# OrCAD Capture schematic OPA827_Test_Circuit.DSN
size A; title: OPA827 Low-Noise, High-Precision, JFET-Input Operational; rev: 1.3; note: Datasheet: SBOS376I  EVM: N/A
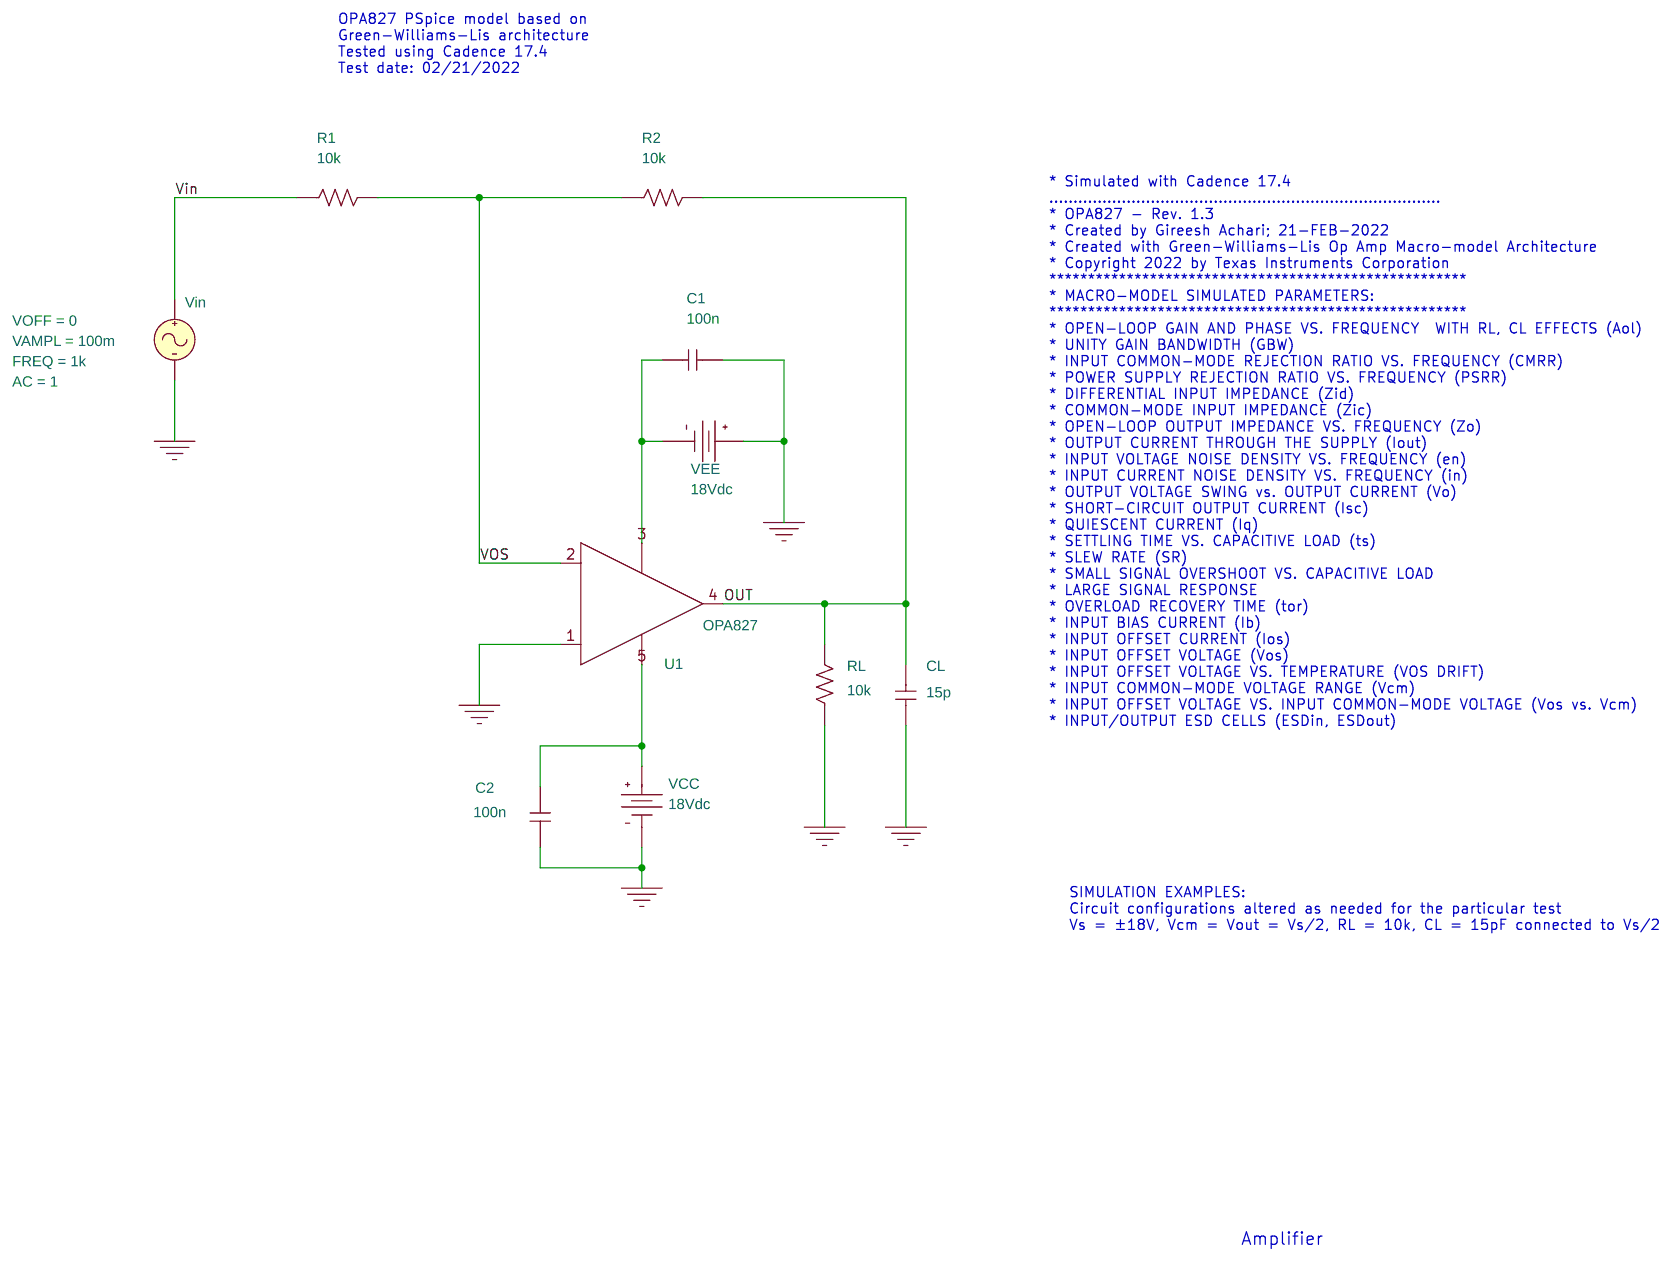
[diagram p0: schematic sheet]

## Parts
C1  100n  [cap196]
C2  100n  [cap196]
CL  15p  [cap196]
R1  10k  [AXRC05]
R2  10k  [AXRC05]
RL  10k  [AXRC05]
U1  OPA827
VCC  VDC
VEE  VDC
Vin  VSIN

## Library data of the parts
C1 C2 CL = C
R1 R2 RL = R
U1 = OPA827
VCC VEE = VDC: DC: 18Vdc
Vin = VSIN: AC: 1; FREQ: 1k; VAMPL: 100m; VOFF: 0

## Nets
Vin: R1.1 Vin.1(+)
0: C1.2 C2.1 CL.2 RL.1 U1.1(+) VCC.1(-) VEE.0(+) Vin.2(-)
OUT: CL.1 R2.2 RL.2 U1.4(OUT)
VOS: R1.2 R2.1 U1.2(-)
N46378: C1.1 U1.3(V-) VEE.1(-)
N46592: C2.2 U1.5(V+) VCC.0(+)

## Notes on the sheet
- OPA827 PSpice model based on
  Green-Williams-Lis architecture
  Tested using Cadence 17.4
  Test date: 02/21/2022
- * Simulated with Cadence 17.4
  .................................................................................
  * OPA827 - Rev. 1.3
  * Created by Gireesh Achari; 21-FEB-2022
  * Created with Green-Williams-Lis Op Amp Macro-model Architecture
  * Copyright 2022 by Texas Instruments Corporation
  ******************************************************
  * MACRO-MODEL SIMULATED PARAMETERS:
  ******************************************************
  * OPEN-LOOP GAIN AND PHASE VS. FREQUENCY  WITH RL, CL EFFECTS (Aol)
  * UNITY GAIN BANDWIDTH (GBW)
  * INPUT COMMON-MODE REJECTION RATIO VS. FREQUENCY (CMRR)
  * POWER SUPPLY REJECTION RATIO VS. FREQUENCY (PSRR)
  * DIFFERENTIAL INPUT IMPEDANCE (Zid)
  * COMMON-MODE INPUT IMPEDANCE (Zic)
  * OPEN-LOOP OUTPUT IMPEDANCE VS. FREQUENCY (Zo)
  * OUTPUT CURRENT THROUGH THE SUPPLY (Iout)
  * INPUT VOLTAGE NOISE DENSITY VS. FREQUENCY (en)
  * INPUT CURRENT NOISE DENSITY VS. FREQUENCY (in)
  * OUTPUT VOLTAGE SWING vs. OUTPUT CURRENT (Vo)
  * SHORT-CIRCUIT OUTPUT CURRENT (Isc)
  * QUIESCENT CURRENT (Iq)
  * SETTLING TIME VS. CAPACITIVE LOAD (ts)
  * SLEW RATE (SR)
  * SMALL SIGNAL OVERSHOOT VS. CAPACITIVE LOAD
  * LARGE SIGNAL RESPONSE
  * OVERLOAD RECOVERY TIME (tor)
  * INPUT BIAS CURRENT (Ib)
  * INPUT OFFSET CURRENT (Ios)
  * INPUT OFFSET VOLTAGE (Vos)
  * INPUT OFFSET VOLTAGE VS. TEMPERATURE (VOS DRIFT)
  * INPUT COMMON-MODE VOLTAGE RANGE (Vcm)
  * INPUT OFFSET VOLTAGE VS. INPUT COMMON-MODE VOLTAGE (Vos vs. Vcm)
  * INPUT/OUTPUT ESD CELLS (ESDin, ESDout)
- SIMULATION EXAMPLES:
  Circuit configurations altered as needed for the particular test
  Vs = ±18V, Vcm = Vout = Vs/2, RL = 10k, CL = 15pF connected to Vs/2
- Amplifier
